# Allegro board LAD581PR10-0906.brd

Outline 320.45 x 178.8 mm; copper layers: TOP, GND1, IN1, GND2, IN2, VCC, IN3, IN4, GND3, IN5, GND4, BOTTOM. Coordinates in mm from the lower left corner of the outline.

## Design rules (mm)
constraint set DEFAULT: min track width 0.114
net group 15/12: nets TBT_A_USB20_NT TBT_A_USB20_PT
net group 18/12: nets H_PECI PECI_KB9012
net group CPU_DP1_0: nets CPU_DP1_N0 CPU_DP1_P0
net group CPU_DP1_0_C: nets CPU_DP1_N0_C CPU_DP1_P0_C
net group CPU_DP1_1: nets CPU_DP1_N1 CPU_DP1_P1
net group CPU_DP1_1_C: nets CPU_DP1_N1_C CPU_DP1_P1_C
net group CPU_DP1_2: nets CPU_DP1_N2 CPU_DP1_P2
net group CPU_DP1_2_C: nets CPU_DP1_N2_C CPU_DP1_P2_C
net group CPU_DP1_3: nets CPU_DP1_N3 CPU_DP1_P3
net group CPU_DP1_3_C: nets CPU_DP1_N3_C CPU_DP1_P3_C
net group CPU_DP1_AUX: nets CPU_DP1_AUXN CPU_DP1_AUXP
net group CPU_DP1_AUX_C: nets CPU_DP1_AUXN_C CPU_DP1_AUXP_C
net group CPU_DP2_0: nets CPU_DP2_N0 CPU_DP2_P0
net group CPU_DP2_0_C: nets CPU_DP2_N0_C CPU_DP2_P0_C
net group CPU_DP2_1: nets CPU_DP2_N1 CPU_DP2_P1
net group CPU_DP2_1_C: nets CPU_DP2_N1_C CPU_DP2_P1_C
net group CPU_DP2_2: nets CPU_DP2_N2 CPU_DP2_P2
net group CPU_DP2_2_C: nets CPU_DP2_N2_C CPU_DP2_P2_C
net group CPU_DP2_3: nets CPU_DP2_N3 CPU_DP2_P3
net group CPU_DP2_3_C: nets CPU_DP2_N3_C CPU_DP2_P3_C
net group CPU_DP2_AUX: nets CPU_DP2_AUXN CPU_DP2_AUXP
net group CPU_DP2_AUX_C: nets CPU_DP2_AUXN_C CPU_DP2_AUXP_C
net group DDR-ALERT: nets DDR_A_ALERT# DDR_B_ALERT#
net group DDRA-CLK: nets M_CLK_DDR1 M_CLK_DDR#1
net group DDRB-CLK: nets M_CLK_DDR2 M_CLK_DDR#2
net group DIFFPAIR47: nets M_CLK_DDR0 M_CLK_DDR#0
net group DIFFPAIR50: nets M_CLK_DDR3 M_CLK_DDR#3
net group DIFFPAIR85: nets TP_CLK TP_DATA
net group DIFFPAIR91: nets TBTA_SBU1 TBTA_SBU2
net group DIFFPAIR93: nets DISP_CLK_AUXP_CONN DISP_DAT_AUXN_CONN
net group DIFFPAIR126: nets PEG_CRX_GTX_N9 PEG_CRX_GTX_P9
net group DIFFPAIR127: nets PEG_CRX_GTX_C_N10 PEG_CRX_GTX_C_P10
net group DIFFPAIR128: nets PEG_CRX_GTX_N10 PEG_CRX_GTX_P10
net group DIFFPAIR129: nets PEG_CRX_GTX_N8 PEG_CRX_GTX_P8
net group DIFFPAIR130: nets PEG_CRX_GTX_C_N11 PEG_CRX_GTX_C_P11
net group DIFFPAIR131: nets PEG_CRX_GTX_N11 PEG_CRX_GTX_P11
net group DIFFPAIR132: nets PEG_CTX_GRX_N10 PEG_CTX_GRX_P10
net group DIFFPAIR133: nets PEG_CTX_C_GRX_N10 PEG_CTX_C_GRX_P10
net group DIFFPAIR134: nets PEG_CTX_GRX_N11 PEG_CTX_GRX_P11
net group DIFFPAIR135: nets PEG_CTX_C_GRX_N11 PEG_CTX_C_GRX_P11
net group DIFFPAIR136: nets PEG_CTX_GRX_N9 PEG_CTX_GRX_P9
net group DIFFPAIR137: nets PEG_CTX_C_GRX_N8 PEG_CTX_C_GRX_P8
net group DIFFPAIR138: nets PEG_CTX_GRX_N8 PEG_CTX_GRX_P8
net group DIFFPAIR139: nets PEG_CTX_C_GRX_N9 PEG_CTX_C_GRX_P9
net group DIFFPAIR140: nets PEG_CTX_C_GRX_N7 PEG_CTX_C_GRX_P7
net group DIFFPAIR141: nets PEG_CTX_C_GRX_N5 PEG_CTX_C_GRX_P5
net group DIFFPAIR142: nets PEG_CTX_C_GRX_N6 PEG_CTX_C_GRX_P6
net group DIFFPAIR143: nets PEG_CTX_C_GRX_N4 PEG_CTX_C_GRX_P4
net group DIFFPAIR144: nets PEG_CTX_C_GRX_N3 PEG_CTX_C_GRX_P3
net group DIFFPAIR145: nets PEG_CTX_C_GRX_N2 PEG_CTX_C_GRX_P2
net group DIFFPAIR146: nets PEG_CTX_C_GRX_N1 PEG_CTX_C_GRX_P1
net group DIFFPAIR147: nets PEG_CTX_C_GRX_N0 PEG_CTX_C_GRX_P0
net group DIFFPAIR148: nets PEG_CRX_GTX_C_N9 PEG_CRX_GTX_C_P9
net group DIFFPAIR149: nets PEG_CRX_GTX_C_N8 PEG_CRX_GTX_C_P8
net group DIFFPAIR151: nets FBC_WCK23 FBC_WCK23#
net group DIFFPAIR152: nets FBC_WCK67 FBC_WCK67#
net group DIFFPAIR153: nets FBB_WCK23 FBB_WCK23#
net group DIFFPAIR154: nets FBB_CLK0 FBB_CLK0#
net group DIFFPAIR155: nets FBB_CLK1 FBB_CLK1#
net group DIFFPAIR156: nets FBB_WCK67 FBB_WCK67#
net group DIFFPAIR157: nets FBA_WCK23 FBA_WCK23#
net group DIFFPAIR158: nets FBA_CLK0 FBA_CLK0#
net group DIFFPAIR159: nets FBA_CLK1 FBA_CLK1#
net group DIFFPAIR160: nets FBA_WCK67 FBA_WCK67#
net group DIFFPAIR163: nets DMIC_CLK1_R DMIC_DATA1_R
net group DIFFPAIR164: nets EC_ESB_CLK EC_ESB_DAT
net group DIFFPAIR165: nets FBC_CLK1 FBC_CLK1#
net group DIFFPAIR166: nets FBC_WCK45 FBC_WCK45#
net group DIFFPAIR167: nets FBC_WCK01 FBC_WCK01#
net group DIFFPAIR168: nets FBA_WCK01 FBA_WCK01#
net group DIFFPAIR175: nets HDMI_CTRLCLK HDMI_CTRLDAT
net group DIFFPAIR176: nets I2CC_SCL I2CC_SDA
net group DIFFPAIR177: nets VGA_SMB_CK2 VGA_SMB_DA2
net group DIFFPAIR178: nets I2CC_SCL_R I2CC_SDA_R
net group DIFFPAIR179: nets FBB_WCK45 FBB_WCK45#
net group DIFFPAIR180: nets FBA_WCK45 FBA_WCK45#
net group DIFFPAIR181: nets FBB_WCK01 FBB_WCK01#
net group DP1: nets DDR_A_DQS0 DDR_A_DQS#0
net group DP3: nets DDR_A_DQS2 DDR_A_DQS#2
net group DP5: nets DDR_A_DQS4 DDR_A_DQS#4
net group DP7: nets DDR_A_DQS6 DDR_A_DQS#6
net group DP9: nets DDR_B_DQS0 DDR_B_DQS#0
net group DP11: nets DDR_B_DQS2 DDR_B_DQS#2
net group DP13: nets DDR_B_DQS4 DDR_B_DQS#4
net group DP15: nets DDR_B_DQS6 DDR_B_DQS#6
net group DP17: nets FBC_CLK0 FBC_CLK0#
net group EDP-GPU: nets GPU_AUXN/DDC_C GPU_AUXP/DDC_C
net group PEG_CRX_TTX_12_C: nets PEG_CRX_TTX_N12_C PEG_CRX_TTX_P12_C
net group PEG_CRX_TTX_13_C: nets PEG_CRX_TTX_N13_C PEG_CRX_TTX_P13_C
net group PEG_CRX_TTX_14_C: nets PEG_CRX_TTX_N14_C PEG_CRX_TTX_P14_C
net group PEG_CRX_TTX_15_C: nets PEG_CRX_TTX_N15_C PEG_CRX_TTX_P15_C
net group PEG_CTX_TRX_12_C: nets PEG_CTX_TRX_N12_C PEG_CTX_TRX_P12_C
net group PEG_CTX_TRX_13_C: nets PEG_CTX_TRX_N13_C PEG_CTX_TRX_P13_C
net group PEG_CTX_TRX_14_C: nets PEG_CTX_TRX_N14_C PEG_CTX_TRX_P14_C
net group PEG_CTX_TRX_15_C: nets PEG_CTX_TRX_N15_C PEG_CTX_TRX_P15_C
net group SW_USB20_1: nets SW_USB20_N1 SW_USB20_P1
net group TBTA_DIG_AUD_: nets TBTA_DIG_AUD_N TBTA_DIG_AUD_P
net group TMDS_L_TX0: nets TMDS_L_TX0N TMDS_L_TX0P
net group TMDS_L_TX1: nets TMDS_L_TX1N TMDS_L_TX1P
net group TMDS_L_TX2: nets TMDS_L_TX2N TMDS_L_TX2P
net group TMDS_L_TXC: nets TMDS_L_TXCN TMDS_L_TXCP
net group 10: nets HPOUT-L HPOUT-R REMOTE1+ REMOTE1- REMOTE2+ REMOTE2- REMOTE3+ REMOTE3- SPK_L+_CONN SPK_L-_CONN SPK_R+_CONN SPK_R-_CONN
net group 12: nets CALDERA_RST# CDRA_RST# CFG0 CFG1 CFG2 CFG3 CFG4 CFG5 CFG6 CFG7 CFG8 CFG9 CFG10 CFG11 CFG12 CFG13 CFG14 CFG15 CFG16 CFG17 CFG18 CFG19 CPU_TRIGGER DGPU_HOLD_RST# DGPU_PEX_RST# DGPU_PWROK H_CPUPWRGD H_DRAMRST# H_PM_DOWN H_PM_SYNC_R H_PROCHOT# H_THERMTRIP# H_THERMTRIP#_R H_VCCST_PWRGD PCH_DPWROK PCH_PLTRST# PCH_PWROK PCH_TRIGGER PLTRST_CPU# SYS_PWROK VCCIO_PGOOD VR_HOT#
net group 15: nets CRX_N8 CRX_N9 CRX_N10 CRX_N11 CRX_P8 CRX_P9 CRX_P10 CRX_P11 PBTN_OUT# PCIE_WAKE# PCIECOMP PCIECOMP# PEG_RCOMP USB2_COMP
net group 19/12: nets DP_AUXN_C DP_AUXP_C EDP_TX0#_C EDP_TX0_C EDP_TX1#_C EDP_TX1_C EDP_TX2#_C EDP_TX2_C EDP_TX3#_C EDP_TX3_C GPU_AUXN/DDC GPU_AUXP/DDC GPU_MDP_N0 GPU_MDP_N1 GPU_MDP_N2 GPU_MDP_N3 GPU_MDP_P0 GPU_MDP_P1 GPU_MDP_P2 GPU_MDP_P3 GPU_TX0N GPU_TX0N_C GPU_TX0P GPU_TX0P_C GPU_TX1N GPU_TX1N_C GPU_TX1P GPU_TX1P_C GPU_TX2N GPU_TX2N_C GPU_TX2P GPU_TX2P_C GPU_TX3N GPU_TX3N_C GPU_TX3P GPU_TX3P_C MDP_LANE_N0_C MDP_LANE_N1_C MDP_LANE_N2_C MDP_LANE_N3_C MDP_LANE_P0_C MDP_LANE_P1_C MDP_LANE_P2_C MDP_LANE_P3_C MUX_EDP_A0N MUX_EDP_A0P MUX_EDP_A1N MUX_EDP_A1P MUX_EDP_A2N MUX_EDP_A2P MUX_EDP_A3N MUX_EDP_A3P TMDS_C_TX0N TMDS_C_TX0P TMDS_C_TX1N TMDS_C_TX1P TMDS_C_TX2N TMDS_C_TX2P TMDS_C_TXCN TMDS_C_TXCP TMDS_CTRLCLK_R TMDS_CTRLDAT_R TMDS_R_TX0N TMDS_R_TX0P TMDS_R_TX1N TMDS_R_TX1P TMDS_R_TX2N TMDS_R_TX2P TMDS_R_TXCN TMDS_R_TXCP TMDS_SCLF TMDS_SDAF TMDS_TX0N TMDS_TX0P TMDS_TX1N TMDS_TX1P TMDS_TX2N TMDS_TX2P TMDS_TXCN TMDS_TXCP
net group 20: nets +V_DDR_REFA +V_DDR_REFA_R +V_DDR_REFB +V_DDR_REFB_R TBT_A_AUX_N TBT_A_AUX_N_C TBT_A_AUX_P TBT_A_AUX_P_C TBT_XTAL_25_IN TBT_XTAL_25_OUT XTAL24_IN XTAL24_OUT XTLI XTLO
net group 25: nets EDP_RCOMP
net group AUDIO: nets HDA_SPKR ME_EN PCH_AZ_BITCLK PCH_AZ_CODEC_BITCLK PCH_AZ_CODEC_RST# PCH_AZ_CODEC_RST#_R PCH_AZ_CODEC_SDIN0 PCH_AZ_CODEC_SDOUT PCH_AZ_CODEC_SYNC PCH_AZ_RST# PCH_AZ_SDOUT PCH_AZ_SYNC
net group B+: nets B+
net group DDR-RCOMP: nets DDR_RCOMP0 DDR_RCOMP1 DDR_RCOMP2
net group DDR-STROBE: nets DDR_A_DQS1 DDR_A_DQS3 DDR_A_DQS5 DDR_A_DQS7 DDR_A_DQS#1 DDR_A_DQS#3 DDR_A_DQS#5 DDR_A_DQS#7 DDR_B_DQS1 DDR_B_DQS3 DDR_B_DQS5 DDR_B_DQS7 DDR_B_DQS#1 DDR_B_DQS#3 DDR_B_DQS#5 DDR_B_DQS#7
net group DDRA-CMD: nets DDR_A_BG0 DDR_A_BG1 DDR_A_BS0 DDR_A_BS1 DDR_A_CAS# DDR_A_MA0 DDR_A_MA1 DDR_A_MA2 DDR_A_MA3 DDR_A_MA4 DDR_A_MA5 DDR_A_MA6 DDR_A_MA7 DDR_A_MA8 DDR_A_MA9 DDR_A_MA10 DDR_A_MA11 DDR_A_MA12 DDR_A_MA13 DDR_A_RAS# DDR_A_WE#
net group DDRA-CTL: nets DDR_A_ACT# DDR_A_PAR DDR_CKE0_DIMMA DDR_CKE1_DIMMA DDR_CS0_DIMMA# DDR_CS1_DIMMA# M_ODT0 M_ODT1
net group DDRA-D0: nets DDR_A_D0 DDR_A_D1 DDR_A_D2 DDR_A_D3 DDR_A_D4 DDR_A_D5 DDR_A_D6 DDR_A_D7
net group DDRA-D1: nets DDR_A_D8 DDR_A_D9 DDR_A_D10 DDR_A_D11 DDR_A_D12 DDR_A_D13 DDR_A_D14 DDR_A_D15
net group DDRA-D2: nets DDR_A_D16 DDR_A_D17 DDR_A_D18 DDR_A_D19 DDR_A_D20 DDR_A_D21 DDR_A_D22 DDR_A_D23
net group DDRA-D3: nets DDR_A_D24 DDR_A_D25 DDR_A_D26 DDR_A_D27 DDR_A_D28 DDR_A_D29 DDR_A_D30 DDR_A_D31
net group DDRA-D4: nets DDR_A_D32 DDR_A_D33 DDR_A_D34 DDR_A_D35 DDR_A_D36 DDR_A_D37 DDR_A_D38 DDR_A_D39
net group DDRA-D5: nets DDR_A_D40 DDR_A_D41 DDR_A_D42 DDR_A_D43 DDR_A_D44 DDR_A_D45 DDR_A_D46 DDR_A_D47
net group DDRA-D6: nets DDR_A_D48 DDR_A_D49 DDR_A_D50 DDR_A_D51 DDR_A_D52 DDR_A_D53 DDR_A_D54 DDR_A_D55
net group DDRA-D7: nets DDR_A_D56 DDR_A_D57 DDR_A_D58 DDR_A_D59 DDR_A_D60 DDR_A_D61 DDR_A_D62 DDR_A_D63
net group DDRB-CMD: nets DDR_B_BG0 DDR_B_BG1 DDR_B_BS0 DDR_B_BS1 DDR_B_CAS# DDR_B_MA0 DDR_B_MA1 DDR_B_MA2 DDR_B_MA3 DDR_B_MA4 DDR_B_MA5 DDR_B_MA6 DDR_B_MA7 DDR_B_MA8 DDR_B_MA9 DDR_B_MA10 DDR_B_MA11 DDR_B_MA12 DDR_B_MA13 DDR_B_RAS# DDR_B_WE#
net group DDRB-CTL: nets DDR_B_ACT# DDR_B_PAR DDR_CKE2_DIMMB DDR_CKE3_DIMMB DDR_CS2_DIMMB# DDR_CS3_DIMMB# M_ODT2 M_ODT3
net group DDRB-D0: nets DDR_B_D0 DDR_B_D1 DDR_B_D2 DDR_B_D3 DDR_B_D4 DDR_B_D5 DDR_B_D6 DDR_B_D7
net group DDRB-D1: nets DDR_B_D8 DDR_B_D9 DDR_B_D10 DDR_B_D11 DDR_B_D12 DDR_B_D13 DDR_B_D14 DDR_B_D15
net group DDRB-D2: nets DDR_B_D16 DDR_B_D17 DDR_B_D18 DDR_B_D19 DDR_B_D20 DDR_B_D21 DDR_B_D22 DDR_B_D23
net group DDRB-D3: nets DDR_B_D24 DDR_B_D25 DDR_B_D26 DDR_B_D27 DDR_B_D28 DDR_B_D29 DDR_B_D30 DDR_B_D31
net group DDRB-D4: nets DDR_B_D32 DDR_B_D33 DDR_B_D34 DDR_B_D35 DDR_B_D36 DDR_B_D37 DDR_B_D38 DDR_B_D39
net group DDRB-D5: nets DDR_B_D40 DDR_B_D41 DDR_B_D42 DDR_B_D43 DDR_B_D44 DDR_B_D45 DDR_B_D46 DDR_B_D47
net group DDRB-D6: nets DDR_B_D48 DDR_B_D49 DDR_B_D50 DDR_B_D51 DDR_B_D52 DDR_B_D53 DDR_B_D54 DDR_B_D55
net group DDRB-D7: nets DDR_B_D56 DDR_B_D57 DDR_B_D58 DDR_B_D59 DDR_B_D60 DDR_B_D61 DDR_B_D62 DDR_B_D63
net group DIFFPAIR46: nets MIC_DATA
net group DMI: nets DMI_CRX_PTX_N0 DMI_CRX_PTX_N1 DMI_CRX_PTX_N2 DMI_CRX_PTX_N3 DMI_CRX_PTX_P0 DMI_CRX_PTX_P1 DMI_CRX_PTX_P2 DMI_CRX_PTX_P3 DMI_CTX_PRX_N0 DMI_CTX_PRX_N1 DMI_CTX_PRX_N2 DMI_CTX_PRX_N3 DMI_CTX_PRX_P0 DMI_CTX_PRX_P1 DMI_CTX_PRX_P2 DMI_CTX_PRX_P3
net group EDP-CPU_12_15: nets CPU_EDP_AUX CPU_EDP_AUX# CPU_EDP_AUX#_C CPU_EDP_AUX_C CPU_EDP_N0_C CPU_EDP_N1_C CPU_EDP_N2_C CPU_EDP_N3_C CPU_EDP_P0_C CPU_EDP_P1_C CPU_EDP_P2_C CPU_EDP_P3_C CPU_EDP_TX0N CPU_EDP_TX0P CPU_EDP_TX1N CPU_EDP_TX1P CPU_EDP_TX2N CPU_EDP_TX2P CPU_EDP_TX3N CPU_EDP_TX3P EDP_AUX#_C EDP_AUX_C MUX_EDP_AUXN MUX_EDP_AUXP
net group EMC: nets BOOT_1.2V BST_1.2V BST_3V BST_5V CPU_XDP_TRST# MIC_CLK RJ45_CT0 RJ45_CT1 RJ45_CT2 RJ45_CT3 SPI_MOCLK TBT_EE_CLK TBT_TCK
net group FBA-CMD: nets FBA_CMD0 FBA_CMD1 FBA_CMD2 FBA_CMD3 FBA_CMD4 FBA_CMD5 FBA_CMD6 FBA_CMD7 FBA_CMD8 FBA_CMD9 FBA_CMD10 FBA_CMD11 FBA_CMD12 FBA_CMD13 FBA_CMD14 FBA_CMD15 FBA_CMD16 FBA_CMD17 FBA_CMD18 FBA_CMD19 FBA_CMD20 FBA_CMD21 FBA_CMD22 FBA_CMD23 FBA_CMD24 FBA_CMD25 FBA_CMD26 FBA_CMD27 FBA_CMD28 FBA_CMD29 FBA_CMD30 FBA_CMD31
net group FBA-D0: nets FBA_D0 FBA_D1 FBA_D2 FBA_D3 FBA_D4 FBA_D5 FBA_D6 FBA_D7
net group FBA-D1: nets FBA_D8 FBA_D9 FBA_D10 FBA_D11 FBA_D12 FBA_D13 FBA_D14 FBA_D15
net group FBA-D2: nets FBA_D16 FBA_D17 FBA_D18 FBA_D19 FBA_D20 FBA_D21 FBA_D22 FBA_D23
net group FBA-D3: nets FBA_D24 FBA_D25 FBA_D26 FBA_D27 FBA_D28 FBA_D29 FBA_D30 FBA_D31
net group FBA-D4: nets FBA_D32 FBA_D33 FBA_D34 FBA_D35 FBA_D36 FBA_D37 FBA_D38 FBA_D39
net group FBA-D5: nets FBA_D40 FBA_D41 FBA_D42 FBA_D43 FBA_D44 FBA_D45 FBA_D46 FBA_D47
net group FBA-D6: nets FBA_D48 FBA_D49 FBA_D50 FBA_D51 FBA_D52 FBA_D53 FBA_D54 FBA_D55
net group FBA-D7: nets FBA_D56 FBA_D57 FBA_D58 FBA_D59 FBA_D60 FBA_D61 FBA_D62 FBA_D63
net group FBA_DBI: nets FBA_DBI0 FBA_DBI1 FBA_DBI2 FBA_DBI3 FBA_DBI4 FBA_DBI5 FBA_DBI6 FBA_DBI7
net group FBA_EDC: nets FBA_EDC0 FBA_EDC1 FBA_EDC2 FBA_EDC3 FBA_EDC4 FBA_EDC5 FBA_EDC6 FBA_EDC7
net group FBB_CMD: nets FBB_CMD0 FBB_CMD1 FBB_CMD2 FBB_CMD3 FBB_CMD4 FBB_CMD5 FBB_CMD6 FBB_CMD7 FBB_CMD8 FBB_CMD9 FBB_CMD10 FBB_CMD11 FBB_CMD12 FBB_CMD13 FBB_CMD14 FBB_CMD15 FBB_CMD16 FBB_CMD17 FBB_CMD18 FBB_CMD19 FBB_CMD20 FBB_CMD21 FBB_CMD22 FBB_CMD23 FBB_CMD24 FBB_CMD25 FBB_CMD26 FBB_CMD27 FBB_CMD28 FBB_CMD29 FBB_CMD30 FBB_CMD31
net group FBB_D0: nets FBB_D0 FBB_D1 FBB_D2 FBB_D3 FBB_D4 FBB_D5 FBB_D6 FBB_D7
net group FBB_D1: nets FBB_D8 FBB_D9 FBB_D10 FBB_D11 FBB_D12 FBB_D13 FBB_D14 FBB_D15
net group FBB_D2: nets FBB_D16 FBB_D17 FBB_D18 FBB_D19 FBB_D20 FBB_D21 FBB_D22 FBB_D23
net group FBB_D3: nets FBB_D24 FBB_D25 FBB_D26 FBB_D27 FBB_D28 FBB_D29 FBB_D30 FBB_D31
net group FBB_D4: nets FBB_D32 FBB_D33 FBB_D34 FBB_D35 FBB_D36 FBB_D37 FBB_D38 FBB_D39
net group FBB_D5: nets FBB_D40 FBB_D41 FBB_D42 FBB_D43 FBB_D44 FBB_D45 FBB_D46 FBB_D47
net group FBB_D6: nets FBB_D48 FBB_D49 FBB_D50 FBB_D51 FBB_D52 FBB_D53 FBB_D54 FBB_D55
net group FBB_D7: nets FBB_D56 FBB_D57 FBB_D58 FBB_D59 FBB_D60 FBB_D61 FBB_D62 FBB_D63
net group FBB_DBI: nets FBB_DBI0 FBB_DBI1 FBB_DBI2 FBB_DBI3 FBB_DBI4 FBB_DBI5 FBB_DBI6 FBB_DBI7
net group FBB_EDC: nets FBB_EDC0 FBB_EDC1 FBB_EDC2 FBB_EDC3 FBB_EDC4 FBB_EDC5 FBB_EDC6 FBB_EDC7
net group FBC_CMD: nets FBC_CMD0 FBC_CMD1 FBC_CMD2 FBC_CMD3 FBC_CMD4 FBC_CMD5 FBC_CMD6 FBC_CMD7 FBC_CMD8 FBC_CMD9 FBC_CMD10 FBC_CMD11 FBC_CMD12 FBC_CMD13 FBC_CMD14 FBC_CMD15 FBC_CMD16 FBC_CMD17 FBC_CMD18 FBC_CMD19 FBC_CMD20 FBC_CMD21 FBC_CMD22 FBC_CMD23 FBC_CMD24 FBC_CMD25 FBC_CMD26 FBC_CMD27 FBC_CMD28 FBC_CMD29 FBC_CMD30 FBC_CMD31
net group FBC_D0: nets FBC_D0 FBC_D1 FBC_D2 FBC_D3 FBC_D4 FBC_D5 FBC_D6 FBC_D7
net group FBC_D1: nets FBC_D8 FBC_D9 FBC_D10 FBC_D11 FBC_D12 FBC_D13 FBC_D14 FBC_D15
net group FBC_D2: nets FBC_D16 FBC_D17 FBC_D18 FBC_D19 FBC_D20 FBC_D21 FBC_D22 FBC_D23
net group FBC_D3: nets FBC_D24 FBC_D25 FBC_D26 FBC_D27 FBC_D28 FBC_D29 FBC_D30 FBC_D31
net group FBC_D4: nets FBC_D32 FBC_D33 FBC_D34 FBC_D35 FBC_D36 FBC_D37 FBC_D38 FBC_D39
net group FBC_D5: nets FBC_D40 FBC_D41 FBC_D42 FBC_D43 FBC_D44 FBC_D45 FBC_D46 FBC_D47
net group FBC_D6: nets FBC_D48 FBC_D49 FBC_D50 FBC_D51 FBC_D52 FBC_D53 FBC_D54 FBC_D55
net group FBC_D7: nets FBC_D56 FBC_D57 FBC_D58 FBC_D59 FBC_D60 FBC_D61 FBC_D62 FBC_D63
net group FBC_DBI: nets FBC_DBI0 FBC_DBI1 FBC_DBI2 FBC_DBI3 FBC_DBI4 FBC_DBI5 FBC_DBI6 FBC_DBI7
net group FBC_EDC: nets FBC_EDC0 FBC_EDC1 FBC_EDC2 FBC_EDC3 FBC_EDC4 FBC_EDC5 FBC_EDC6 FBC_EDC7
net group I2C: nets I2C_CLK I2C_DAT TBT_I2C_SCL TBT_I2C_SDA TBTA_I2C_INT TBTB_I2C_INT
net group LAN: nets LAN_MDIN0 LAN_MDIN1 LAN_MDIN2 LAN_MDIN3 LAN_MDIP0 LAN_MDIP1 LAN_MDIP2 LAN_MDIP3 RJ45_MDI0+ RJ45_MDI0- RJ45_MDI1+ RJ45_MDI1- RJ45_MDI2+ RJ45_MDI2- RJ45_MDI3+ RJ45_MDI3-
net group LPC: nets LPC_AD0 LPC_AD1 LPC_AD2 LPC_AD3 LPC_FRAME#
net group MDP-GPU: nets GPU_DPC_AUX GPU_DPC_AUX# MDP_AUX#_SDA MDP_AUX_SCL
net group PCIE: nets PCIE_PRX_DTX_N5 PCIE_PRX_DTX_N5_C PCIE_PRX_DTX_N6 PCIE_PRX_DTX_N9 PCIE_PRX_DTX_N10 PCIE_PRX_DTX_N11 PCIE_PRX_DTX_N12 PCIE_PRX_DTX_N13 PCIE_PRX_DTX_N14 PCIE_PRX_DTX_N15 PCIE_PRX_DTX_N16 PCIE_PRX_DTX_P5 PCIE_PRX_DTX_P5_C PCIE_PRX_DTX_P6 PCIE_PRX_DTX_P9 PCIE_PRX_DTX_P10 PCIE_PRX_DTX_P11 PCIE_PRX_DTX_P12 PCIE_PRX_DTX_P13 PCIE_PRX_DTX_P14 PCIE_PRX_DTX_P15 PCIE_PRX_DTX_P16 PCIE_PTX_DRX_N5 PCIE_PTX_DRX_N5_C PCIE_PTX_DRX_N6 PCIE_PTX_DRX_N6_C PCIE_PTX_DRX_N9 PCIE_PTX_DRX_N9_C PCIE_PTX_DRX_N10 PCIE_PTX_DRX_N10_C PCIE_PTX_DRX_N11 PCIE_PTX_DRX_N11_C PCIE_PTX_DRX_N12 PCIE_PTX_DRX_N12_C PCIE_PTX_DRX_N13 PCIE_PTX_DRX_N13_C PCIE_PTX_DRX_N14 PCIE_PTX_DRX_N14_C PCIE_PTX_DRX_N15 PCIE_PTX_DRX_N15_C PCIE_PTX_DRX_N16 PCIE_PTX_DRX_N16_C PCIE_PTX_DRX_P5 PCIE_PTX_DRX_P5_C PCIE_PTX_DRX_P6 PCIE_PTX_DRX_P6_C PCIE_PTX_DRX_P9 PCIE_PTX_DRX_P9_C PCIE_PTX_DRX_P10 PCIE_PTX_DRX_P10_C PCIE_PTX_DRX_P11 PCIE_PTX_DRX_P11_C PCIE_PTX_DRX_P12 PCIE_PTX_DRX_P12_C PCIE_PTX_DRX_P13 PCIE_PTX_DRX_P13_C PCIE_PTX_DRX_P14 PCIE_PTX_DRX_P14_C PCIE_PTX_DRX_P15 PCIE_PTX_DRX_P15_C PCIE_PTX_DRX_P16 PCIE_PTX_DRX_P16_C
net group PEG: nets PEG_CRX_GTX_N0 PEG_CRX_GTX_N0_C PEG_CRX_GTX_N1 PEG_CRX_GTX_N1_C PEG_CRX_GTX_N2 PEG_CRX_GTX_N2_C PEG_CRX_GTX_N3 PEG_CRX_GTX_N3_C PEG_CRX_GTX_N4 PEG_CRX_GTX_N4_C PEG_CRX_GTX_N5 PEG_CRX_GTX_N5_C PEG_CRX_GTX_N6 PEG_CRX_GTX_N6_C PEG_CRX_GTX_N7 PEG_CRX_GTX_N7_C PEG_CRX_GTX_P0 PEG_CRX_GTX_P0_C PEG_CRX_GTX_P1 PEG_CRX_GTX_P2 PEG_CRX_GTX_P2_C PEG_CRX_GTX_P3 PEG_CRX_GTX_P3_C PEG_CRX_GTX_P4 PEG_CRX_GTX_P4_C PEG_CRX_GTX_P5 PEG_CRX_GTX_P5_C PEG_CRX_GTX_P6 PEG_CRX_GTX_P6_C PEG_CRX_GTX_P7 PEG_CRX_GTX_P7_C PEG_CRX_TTX_N12 PEG_CRX_TTX_N13 PEG_CRX_TTX_N14 PEG_CRX_TTX_N15 PEG_CRX_TTX_P12 PEG_CRX_TTX_P13 PEG_CRX_TTX_P14 PEG_CRX_TTX_P15 PEG_CTX_GRX_N0 PEG_CTX_GRX_N1 PEG_CTX_GRX_N2 PEG_CTX_GRX_N3 PEG_CTX_GRX_N4 PEG_CTX_GRX_N5 PEG_CTX_GRX_N6 PEG_CTX_GRX_N7 PEG_CTX_GRX_P0 PEG_CTX_GRX_P1 PEG_CTX_GRX_P2 PEG_CTX_GRX_P3 PEG_CTX_GRX_P4 PEG_CTX_GRX_P5 PEG_CTX_GRX_P6 PEG_CTX_GRX_P7 PEG_CTX_TRX_N12 PEG_CTX_TRX_N13 PEG_CTX_TRX_N14 PEG_CTX_TRX_N15 PEG_CTX_TRX_P12 PEG_CTX_TRX_P13 PEG_CTX_TRX_P14 PEG_CTX_TRX_P15
net group PEG_CRX_GTX_1_C: nets PEG_CRX_GTX_P1_C
net group PLATFORM-CLK: nets CLK_PCI_LPC CLK_PCIE_DGPU#_C CLK_PCIE_DGPU_C CLK_PCIE_N1 CLK_PCIE_N2 CLK_PCIE_N3 CLK_PCIE_N4 CLK_PCIE_N5 CLK_PCIE_N6 CLK_PCIE_P1 CLK_PCIE_P2 CLK_PCIE_P3 CLK_PCIE_P4 CLK_PCIE_P5 CLK_PCIE_P6 CLK_PEG_GPU CLK_PEG_GPU# CPU_24MHZ_N CPU_24MHZ_P PCH_CPU_BCLK_N PCH_CPU_BCLK_P PCH_CPU_PCIBCLK_N PCH_CPU_PCIBCLK_P PCH_XDP_CLK_N PCH_XDP_CLK_P
net group POWER: nets +0.6VS +0.6VSP +0.9V_CIO +0.9V_DP +0.9V_LVR_OUT +0.9V_PCIE +0.9V_SVR +0.9V_USB +1.2V_DDR +1.2V_VCCPLL_OC +1.2VP +1.8VA_TBTA_LDO +1.8VD_TBTA_LDO +1.35VS_VGA_PGOOD +1V_MPHY +1V_PCH +1V_PCH_PRIM +1V_VCCDSW +1VALWP +1VALWP_B+ +2.5V_MEM +2.5V_MEMP +2.5VOUT +2.5VSP_ON +3.3V_1.8V_DVDD +3.3V_1.8V_DVDD_IO +3.3V_ANA_PCIE +3.3V_ANA_USB2 +3.3V_F383 +3.3V_FLASH +3.3V_LC +3.3V_TBT_SX +3.3V_TBT_SX_R +3V_PCH +3VALW_PCH +3VALW_PD +3VALWP +3VLP +3VS_CAM +3VS_DP +3VS_TBT +3VS_TOUCH +5V_PVDD +5V_USB_PWR1 +5V_USB_PWR2 +5V_USBC_VBUS +5VA +5VALW_LED +5VALWP +5VS +5VS_TP_LED +AVDDH +AVDDL +CODEC_AVDD2 +DVDDL +EC_VCCA +HDMI_5V_OUT +INV_PWR_SRC +LAN_IO +LCDVDD +PVDD +RBIAS +RTC_CELL +TBTA_VBUS +V18R +VCCIOP +VCCST +VCCSTG +VDD_TOUCH +VDDCT_L
net group RTC: nets PCH_RTCRST# PCH_RTCX1 PCH_RTCX2 PCH_SRTCRST#
net group SENSE: nets VCCGT_SENSE VCCIO_SENSE VCCSA_SENSE VCCSENSE VSSGT_SENSE VSSIO_SENSE VSSSA_SENSE VSSSENSE
net group SMBUS: nets CLK_SMB CPU_DDC1CLK CPU_DDC1DATA CPU_DDC2CLK CPU_DDC2DATA DAT_SMB EC_SMB_CK1 EC_SMB_CK2 EC_SMB_DA1 EC_SMB_DA2 IN1_PEQ# IN2_PEQ# PCH_SMBCLK PCH_SMBDATA SML0CLK SML0DATA SML1CLK SML1DATA
net group SPI: nets PCH_SPI_CLK PCH_SPI_CLK_R PCH_SPI_CS# PCH_SPI_HOLD# PCH_SPI_HOLD#_R PCH_SPI_SI PCH_SPI_SI_R PCH_SPI_SO PCH_SPI_SO_R PCH_SPI_WP# PCH_SPI_WP#_R PCH_SYS_PWROK_XDP
net group SVID: nets VR_SVID_ALERT# VR_SVID_CLK VR_SVID_DATA
net group TBT: nets USB3_A_TRX_DTX_N0 USB3_A_TRX_DTX_N1 USB3_A_TRX_DTX_P0 USB3_A_TRX_DTX_P1 USB3_A_TTX_C_DRX_N0 USB3_A_TTX_C_DRX_N1 USB3_A_TTX_C_DRX_P0 USB3_A_TTX_C_DRX_P1 USB3_A_TTX_DRX_N0 USB3_A_TTX_DRX_N1 USB3_A_TTX_DRX_P0 USB3_A_TTX_DRX_P1
net group USB20: nets TBT_A_USB20_L_NB TBT_A_USB20_L_NT TBT_A_USB20_L_PB TBT_A_USB20_L_PT TBT_A_USB20_N TBT_A_USB20_NB TBT_A_USB20_P TBT_A_USB20_PB USB20_CAM_N7_R USB20_CAM_P7_R USB20_N1 USB20_N1_CONN USB20_N2 USB20_N2_CONN USB20_N3 USB20_N3_CONN USB20_N4 USB20_N5 USB20_N6 USB20_N7 USB20_N8 USB20_N8_CONN USB20_P1 USB20_P1_CONN USB20_P2 USB20_P2_CONN USB20_P3 USB20_P3_CONN USB20_P4 USB20_P5 USB20_P6 USB20_P7 USB20_P8 USB20_P8_CONN
net group USB30: nets USB3_CRX_L_DTX_N1 USB3_CRX_L_DTX_N2 USB3_CRX_L_DTX_N4 USB3_CRX_L_DTX_N5 USB3_CRX_L_DTX_P1 USB3_CRX_L_DTX_P2 USB3_CRX_L_DTX_P4 USB3_CRX_L_DTX_P5 USB3_CTX_C_DRX_N1 USB3_CTX_C_DRX_N2 USB3_CTX_C_DRX_N4 USB3_CTX_C_DRX_N5 USB3_CTX_C_DRX_P1 USB3_CTX_C_DRX_P2 USB3_CTX_C_DRX_P4 USB3_CTX_C_DRX_P5 USB3_CTX_C_L_DRX_N1 USB3_CTX_C_L_DRX_N2 USB3_CTX_C_L_DRX_N4 USB3_CTX_C_L_DRX_N5 USB3_CTX_C_L_DRX_P1 USB3_CTX_C_L_DRX_P2 USB3_CTX_C_L_DRX_P4 USB3_CTX_C_L_DRX_P5 USB3RN1 USB3RN2 USB3RN3 USB3RN4 USB3RN5 USB3RP1 USB3RP2 USB3RP3 USB3RP4 USB3RP5 USB3TN1 USB3TN2 USB3TN3 USB3TN4 USB3TN5 USB3TP1 USB3TP2 USB3TP3 USB3TP4 USB3TP5
net group XDP: nets XDP_PRDY# XDP_PREQ# XDP_TMS
nets with their own width: min track width 0.254; nets ECAGND HP2_D_L_C HP2_D_R_C LINE1_L LINE1_R NVVDD_VCC_SENSE NVVDD_VSS_SENSE NVVDDS_VCC_SENSE NVVDDS_VSS_SENSE
nets with their own width: min track width 0.356; nets +1V8_AON
nets with their own width: min track width 0.381; nets MEM_VREF
nets with their own width: min track width 0.406; nets +FBA_VREFC +FBB_VREFC +FBC_VREFC
nets with their own width: min track width 0.508; nets +1.35VS_VGA +1V8_MAIN +1VALW +3V3_SYS +3VALW +3VS +5VALW +FBX_PLLAVDD +IFPX_PLLVDD +VCC_CORE +VCCGT +VCCIO +VCCSA GND GNDA N19616464
nets with their own width: min track width 1.016; nets +1.8VS ISENSEP_L ISENSEP_L_R ISENSEP_R ISENSEP_R_R IVSENSE_L IVSENSE_R RJ45_CT VSENSEN_L VSENSEN_R
nets with their own width: min track width 1.524; nets B+_BIAS
nets with their own width: min track width 5.08; nets +3VS_SSD

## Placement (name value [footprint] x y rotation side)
C2  0.1U_0402_10V6K  [C_0402]  215.09 8.08 90 top
C3  2200P_0402_25V7K  [C_0402]  98.52 92.98 180 bottom
C4  1U_0402_6.3V6K  [C_0402]  147.46 72.6 180 top
C6  0.1U_0402_10V7K  [C_0402]  148.84 77.64 0 top
C7  1U_0402_6.3V6K  [C_0402]  152.46 70.34 0 top
C10  0.1U_0402_10V7K  [C_0402]  152.97 77.64 0 top
C11  0.1U_0402_10V7K  [C_0402]  100.48 93.65 270 bottom
C29  0.1U_0402_16V4Z  [C_0402]  197.69 4.27 90 top
C256  10U_0603_6.3V6M  [C_0603]  62.81 55.76 270 bottom
C257  10U_0603_6.3V6M  [C_0603]  61.54 55.76 270 bottom
C258  0.1U_0402_16V7K  [C_0402]  54.75 60.78 180 bottom
C260  10U_0603_6.3V6M  [C_0603]  63.32 66.51 0 top
C261  10U_0603_6.3V6M  [C_0603]  63.32 65.24 0 top
C262  10U_0603_6.3V6M  [C_0603]  54.3 63.32 90 bottom
C263  0.1U_0402_10V7K  [C_0402]  55.39 63.77 90 bottom
C264  10U_0603_6.3V6M  [C_0603]  56.33 55.7 270 bottom
C265  0.1U_0402_10V7K  [C_0402]  55.12 55.7 270 bottom
C266  10U_0603_6.3V6M  [C_0603]  158.57 60.92 90 top
C267  10U_0603_6.3V6M  [C_0603]  159.84 60.92 90 top
C268  0.01U_0402_16V  [C_0402]  149.87 62.18 90 top
C269  10U_0603_6.3V6M  [C_0603]  147.14 58.13 90 top
C270  0.1U_0402_10V7K  [C_0402]  148.35 58.43 90 top
C617  33P_0402_50V8J  [C_0402]  231.92 44.97 180 top
C618  33P_0402_50V8J  [C_0402]  231.92 44.08 180 top
C620  33P_0402_50V8J  [C_0402]  234.91 3.07 180 top
C621  0.047U_0402_16V4Z  [C_0402]  229.63 27.32 180 top
C622  22U_0402_6.3V8J  [C_0402]  231.93 41.49 180 top
C623  0.047U_0402_16V4Z  [C_0402]  229.63 28.21 180 top
C624  22U_0402_6.3V8J  [C_0402]  234.91 3.96 180 top
C625  0.047U_0402_16V4Z  [C_0402]  234.06 17.3 0 top
C627  0.047U_0402_16V4Z  [C_0402]  234.05 20.84 0 top
C628  33P_0402_50V8J  [C_0402]  234.91 2.18 180 top
C635  22U_0402_6.3V8J  [C_0402]  231.93 42.38 180 top
C636  22U_0402_6.3V8J  [C_0402]  231.93 40.6 180 top
C637  22U_0402_6.3V8J  [C_0402]  234.06 18.19 0 top
C638  22U_0402_6.3V8J  [C_0402]  234.06 19.96 0 top
C2498  0.1U_0402_10V6K  [C_0402]  71.14 58.51 225 bottom
C2500  2200P_0402_25V7K  [C_0402]  107.12 130.35 0 bottom
C2502  2200P_0402_25V7K  [C_0402]  68.55 57.54 225 bottom
C2504  2200P_0402_25V7K  [C_0402]  66.76 59.21 225 bottom
C2505  2200P_0402_25V7K  [C_0402]  192.53 29.11 0 top
C2506  220P_0402_50V8J  [C_0402]  59.94 59.9 0 bottom
C2507  470P_0402_50V7K  [C_0402]  59.94 60.91 0 bottom
C2508  1U_0402_6.3V  [C_0402]  198.59 6.06 180 top
C2509  0.1U_0402_25V6K~D  [C_0402]  203.34 2.89 270 top
C2510  2200P_0402_25V7K  [C_0402]  66.12 59.91 225 bottom
C2511  2200P_0402_25V7K  [C_0402]  220.47 36.79 0 bottom
C2512  10U_0603_6.3V6M  [C_0603]  237.69 15.96 90 top
C2513  10U_0603_6.3V6M  [C_0603]  238.9 15.96 90 top
C2514  10U_0603_6.3V6M  [C_0603]  245.7 14.57 90 top
C2515  10U_0603_6.3V6M  [C_0603]  244.43 14.57 90 top
C2516  0.1U_0402_10V7K  [C_0402]  243.59 17.93 0 top
C2518  0.1U_0402_10V7K  [C_0402]  99.33 87.1 270 bottom
C2519  0.1U_0402_10V7K  [C_0402]  97.94 87.72 180 bottom
C2520  0.1U_0402_10V7K  [C_0402]  153.3 72.16 270 top
C2521  0.1U_0402_10V7K  [C_0402]  297.45 61.49 90 top
C2522  0.1U_0402_10V7K  [C_0402]  151.86 57.81 180 top
C2523  0.1U_0402_10V7K  [C_0402]  59.96 58.95 0 bottom
C2524  0.1U_0402_10V7K  [C_0402]  59.76 61.81 0 bottom
C2525  0.1U_0402_10V7K  [C_0402]  56.53 55.52 0 top
CA1  4.7U_0402_6.3V6M  [C_0402]  28.25 31.7 0 bottom
CA2  0.1U_0402_16V7K  [C_0402]  28.25 32.59 0 bottom
CA3  10U_0603_6.3V6M  [C_0603]  24.96 44.46 0 bottom
CA4  0.1U_0402_16V7K  [C_0402]  25.2 43.39 0 bottom
CA5  10U_0603_6.3V6M  [C_0603]  26.23 45.8 0 bottom
CA6  0.1U_0402_16V7K  [C_0402]  26.47 46.88 0 bottom
CA7  10U_0603_6.3V6M  [C_0603]  27.75 44.46 180 top
CA8  0.1U_0402_16V7K  [C_0402]  27.51 43.39 180 top
CA9  10U_0603_6.3V6M  [C_0603]  27.75 45.67 180 top
CA10  0.1U_0402_16V7K  [C_0402]  27.51 46.75 180 top
CA11  10P_0402_50V8J  [C_0402]  33.65 35.32 0 bottom
CA12  0.1U_0402_16V7K  [C_0402]  31.88 38.23 90 bottom
CA13  4.7U_0402_6.3V6M  [C_0402]  32.77 38.23 90 bottom
CA14  10U_0603_6.3V6M  [C_0603]  23.56 44.21 180 bottom
CA15  0.1U_0402_16V7K  [C_0402]  23.13 43.13 180 bottom
CA16  0.1U_0402_16V7K  [C_0402]  23.82 32.6 270 top
CA17  10U_0603_6.3V6M  [C_0603]  22.74 32.59 270 top
CA18  22P_0402_50V8J  [C_0402]  31.31 32.09 270 bottom
CA19  0.1U_0402_16V7K  [C_0402]  27.58 28.72 135 top
CA20  2.2U_0402_6.3V6M  [C_0402]  24.77 32.59 180 bottom
CA21  2.2U_0402_6.3V6M  [C_0402]  24.68 34.53 180 top
CA23  0.1U_0402_16V7K  [C_0402]  29.09 32.67 270 top
CA24  2.2U_0402_6.3V6M  [C_0402]  21.62 35.75 270 bottom
CA25  2.2U_0402_6.3V6M  [C_0402]  22.87 34.32 90 top
CA26  0.1U_0402_16V7K  [C_0402]  21.04 42.64 180 top
CA27  2.2U_0402_6.3V6M  [C_0402]  21.04 41.75 180 top
CA28  0.1U_0402_16V7K  [C_0402]  26.5 32.59 180 bottom
CA29  10U_0603_6.3V6M  [C_0603]  26.61 31.51 180 bottom
CA30  0.1U_0402_16V7K  [C_0402]  25.59 32.6 270 top
CA31  4.7U_0603_6.3V6M  [C_0603]  26.67 32.53 270 top
CA32  10U_0603_6.3V6M  [C_0603]  23.37 43.07 180 top
CA33  10U_0603_6.3V6M  [C_0603]  21.37 40.69 180 top
CA34  10P_0402_50V8J  [C_0402]  29.72 45.4 90 bottom
CA35  22P_0402_50V8J  [C_0402]  30.87 45.4 90 bottom
CA36  22P_0402_50V8J  [C_0402]  33.46 40.34 0 bottom
CA37  22P_0402_50V8J  [C_0402]  33.46 41.23 0 bottom
CA38  22P_0402_50V8J  [C_0402]  33.46 42.62 0 top
CA39  22P_0402_50V8J  [C_0402]  33.46 42.62 0 bottom
CA40  22P_0402_50V8J  [C_0402]  31.89 40.93 270 top
CA41  0.1U_0402_10V7K  [C_0402]  31.87 37.35 0 bottom
CA42  100P_0201_50V  [C_0201]  15.04 15.48 0 top
CA43  100P_0201_50V  [C_0201]  16.14 23.42 180 top
CA44  0.01U_0201_16V7K  [C_0201]  15.76 25.65 270 top
CA45  680P_0201_50V  [C_0201]  15.19 21.75 90 bottom
CA46  680P_0201_50V  [C_0201]  15.25 16.82 270 bottom
CA47  330U_D2E_6.3VM_R25M  [C_D2E]  15.75 31.11 0 bottom
CA48  100P_0201_50V  [C_0201]  15.75 30.89 270 top
CA49  330U_D2E_6.3VM_R25M  [C_D2E]  18.83 35.54 90 bottom
CA50  100P_0201_50V  [C_0201]  15.7 36.02 180 top
CA51  0.01U_0201_16V7K  [C_0201]  15.21 26.11 90 bottom
CA52  10U_0603_25V6M  [C_0603]  30.68 15.96 270 top
CA53  0.1U_0402_25V7K  [C_0402]  31.62 16.89 90 top
CA54  1000P_0402_50V7K  [C_0402]  30.75 16.89 90 top
CA55  10U_0603_25V6M  [C_0603]  22.11 16.28 270 top
CA56  0.1U_0402_25V7K  [C_0402]  22.55 17.48 0 bottom
CA57  1000P_0402_50V7K  [C_0402]  22.55 18.37 0 bottom
CA58  10U_0402_6.3V6M  [C_0402]  27.5 24.98 270 bottom
CA59  0.1U_0402_16V7K  [C_0402]  26.62 24.95 270 bottom
CA60  0.1U_0402_16V7K  [C_0402]  25.73 24.95 270 bottom
CA61  10U_0603_25V  [C_0603]  21.73 22.19 0 bottom
CA62  0.1U_0402_25V7K  [C_0402]  22.22 21.1 0 bottom
CA63  1000P_0402_50V7K  [C_0402]  22.22 20.21 0 bottom
CA64  10U_0402_6.3V6M  [C_0402]  28.38 26.43 0 bottom
CA65  0.1U_0402_16V7K  [C_0402]  28.38 27.32 0 bottom
CA66  1U_0402_16V6K  [C_0402]  23.13 19.26 180 bottom
CA67  .033U_0603_50V7  [C_0603]  28.65 18.12 0 bottom
CA68  .033U_0603_50V7  [C_0603]  27.76 15.42 180 top
CA69  .033U_0603_50V7  [C_0603]  23.94 15.42 0 top
CA70  .033U_0603_50V7  [C_0603]  22.29 16.27 180 bottom
CA71  1U_0402_16V6K  [C_0402]  29.75 19.15 180 bottom
CA74  0.1U_0402_16V7K  [C_0402]  25.72 26.42 90 bottom
CA77  10U_0402_6.3V6M  [C_0402]  26.76 26.44 90 top
CA78  0.1U_0402_16V7K  [C_0402]  27.62 26.44 90 top
CA79  10U_0603_25V6M  [C_0603]  26.29 13.67 0 bottom
CA80  0.1U_0402_25V7K  [C_0402]  26.53 14.72 0 bottom
CA81  1000P_0402_50V7K  [C_0402]  26.53 15.61 0 bottom
CA82  10U_0603_25V6M  [C_0603]  25.28 13.67 180 bottom
CA83  0.1U_0402_25V7K  [C_0402]  25.1 14.71 180 bottom
CA84  1000P_0402_50V7K  [C_0402]  25.1 15.6 180 bottom
CA85  10U_0402_6.3V6M  [C_0402]  29.98 32.67 270 top
CA87  330P_0402_50V7K  [C_0402]  28.65 14.22 270 bottom
CA88  330P_0402_50V7K  [C_0402]  28.69 14.39 180 top
CA89  330P_0402_50V7K  [C_0402]  23.4 14.39 0 top
CA90  330P_0402_50V7K  [C_0402]  22.06 15.16 180 bottom
CA91  680P_0402_50V8J  [C_0402]  16.13 22.88 0 bottom
CA92  680P_0402_50V8J  [C_0402]  16.7 14.31 0 bottom
CA254  1000P_0402_50V7K  [C_0402]  31.25 13.9 270 bottom
CA255  1000P_0402_50V7K  [C_0402]  28.73 12.36 180 top
CA256  1000P_0402_50V7K  [C_0402]  24.27 12.38 0 top
CA257  1000P_0402_50V7K  [C_0402]  20.22 13.38 180 bottom
CA258  0.1U_0402_10V7K  [C_0402]  19.12 26 0 bottom
CA259  0.1U_0402_10V7K  [C_0402]  36.21 37.69 270 top
CC1  0.22U_0201_6.3V  [C_0201]  173.27 97.56 0 bottom
CC2  0.22U_0201_6.3V  [C_0201]  171.81 98.88 0 bottom
CC3  0.22U_0201_6.3V  [C_0201]  173.2 99.85 0 bottom
CC4  0.22U_0201_6.3V  [C_0201]  171.81 101.12 0 bottom
CC5  0.22U_0201_6.3V  [C_0201]  173.27 102.26 0 bottom
CC6  0.22U_0201_6.3V  [C_0201]  171.81 103.08 0 bottom
CC7  0.22U_0201_6.3V  [C_0201]  173.27 104.15 0 bottom
CC8  0.22U_0201_6.3V  [C_0201]  171.81 105.24 0 bottom
CC9  0.22U_0201_6.3V  [C_0201]  121.24 165.34 90 bottom
CC10  0.22U_0201_6.3V  [C_0201]  122.38 167.12 90 bottom
CC11  0.22U_0201_6.3V  [C_0201]  123.59 165.34 90 bottom
CC12  0.22U_0201_6.3V  [C_0201]  124.79 167.12 90 bottom
CC13  0.22U_0201_6.3V  [C_0201]  173.27 96.93 0 bottom
CC14  0.22U_0201_6.3V  [C_0201]  171.81 97.88 0 bottom
CC15  0.22U_0201_6.3V  [C_0201]  173.2 99.21 0 bottom
CC16  0.22U_0201_6.3V  [C_0201]  171.81 100.46 0 bottom
CC17  0.22U_0201_6.3V  [C_0201]  173.27 101.54 0 bottom
CC18  0.22U_0201_6.3V  [C_0201]  171.81 102.45 0 bottom
CC19  0.22U_0201_6.3V  [C_0201]  173.27 103.45 0 bottom
CC20  0.22U_0201_6.3V  [C_0201]  171.81 104.61 0 bottom
CC21  0.22U_0201_6.3V  [C_0201]  120.6 165.34 90 bottom
CC22  0.22U_0201_6.3V  [C_0201]  121.74 167.12 90 bottom
CC23  0.22U_0201_6.3V  [C_0201]  122.95 165.34 90 bottom
CC24  0.22U_0201_6.3V  [C_0201]  124.16 167.12 90 bottom
CD1  1U_0402_6.3V6K~D  [C_0402]  143.45 50.29 270 top
CD2  1U_0402_6.3V6K~D  [C_0402]  133.48 50.35 270 top
CD3  1U_0402_6.3V6K~D  [C_0402]  149.41 50.53 0 top
CD4  1U_0402_6.3V6K~D  [C_0402]  149.41 49.64 0 top
CD5  10U_0603_6.3V6M~D  [C_0603]  120.34 50.47 270 top
CD6  10U_0603_6.3V6M~D  [C_0603]  114.24 50.47 270 top
CD7  10U_0603_6.3V6M~D  [C_0603]  110.24 50.47 270 top
CD8  10U_0603_6.3V6M~D  [C_0603]  109.8 41.13 90 top
CD9  10U_0603_6.3V6M~D  [C_0603]  148.85 51.61 0 top
CD10  10U_0603_6.3V6M~D  [C_0603]  148.85 52.81 0 top
CD11  220U_D7_2VM_R6M  [C_EEFSS0D221R]  133.48 69.06 0 top
CD12  1U_0402_6.3V6K~D  [C_0402]  148.04 39.61 180 top
CD13  10U_0603_6.3V6M~D  [C_0603]  148.34 41.13 180 top
CD14  10U_0603_6.3V6M~D  [C_0603]  148.34 38.46 180 top
CD15  10U_0603_6.3V6M~D  [C_0603]  148.34 42.34 180 top
CD16  0.1U_0402_16V7K~D  [C_0402]  146.96 52.75 180 top
CD17  2.2U_0603_6.3V6K~D  [C_0603]  147.2 53.83 180 top
CD18  0.1U_0402_16V7K~D  [C_0402]  124.78 41.25 90 top
CD19  1U_0402_6.3V6K~D  [C_0402]  100.53 37.59 270 top
CD20  1U_0402_6.3V6K~D  [C_0402]  133.55 37.59 270 top
CD21  1U_0402_6.3V6K~D  [C_0402]  104.72 29.08 270 top
CD22  1U_0402_6.3V6K~D  [C_0402]  85.23 28.5 270 top
CD23  10U_0603_6.3V6M~D  [C_0603]  110.81 28.37 90 top
CD24  10U_0603_6.3V6M~D  [C_0603]  120.53 37.64 270 top
CD25  10U_0603_6.3V6M~D  [C_0603]  124.15 37.64 270 top
CD26  10U_0603_6.3V6M~D  [C_0603]  113.54 28.37 90 top
CD27  10U_0603_6.3V6M~D  [C_0603]  150.63 38.08 0 top
CD28  10U_0603_6.3V6M~D  [C_0603]  150.63 39.29 0 top
CD29  0.1U_0402_16V7K~D  [C_0402]  124.77 29.32 0 top
CD30  1U_0402_6.3V6K~D  [C_0402]  150.87 37 0 top
CD31  1U_0402_6.3V6K~D  [C_0402]  150.87 36.11 0 top
CD32  1U_0402_6.3V6K~D  [C_0402]  149.75 29.89 180 top
CD33  220U_D7_2VM_R6M  [C_EEFSS0D221R]  129.59 69.07 180 top
CD34  0.1U_0402_16V7K~D  [C_0402]  147.78 35.67 180 top
CD35  2.2U_0603_6.3V6K~D  [C_0603]  148.34 36.75 180 top
CD69  0.1U_0402_16V7K~D  [C_0402]  107.27 42.84 270 top
CD70  10U_0603_6.3V6M~D  [C_0603]  123.77 50.47 270 top
CD71  10U_0603_6.3V6M~D  [C_0603]  117.16 41.13 90 top
CD72  10U_0603_6.3V6M~D  [C_0603]  122.24 41.13 90 top
CD73  10U_0603_6.3V6M~D  [C_0603]  112.84 41.13 90 top
CD74  1U_0402_6.3V6K~D  [C_0402]  138.82 42.22 270 top
CD75  1U_0402_6.3V6K~D  [C_0402]  95.25 41.25 90 top
CD76  1U_0402_6.3V6K~D  [C_0402]  105.49 41.92 90 top
CD77  1U_0402_6.3V6K~D  [C_0402]  128.27 42.22 270 top
CD78  1U_0402_6.3V6K~D  [C_0402]  100.46 50.41 270 top
CD79  1U_0402_6.3V6K~D  [C_0402]  89.86 50.35 270 top
CD80  1U_0402_6.3V6K~D  [C_0402]  128.33 28.43 0 top
CD81  1U_0402_6.3V6K~D  [C_0402]  138.75 28.42 90 top
CD82  1U_0402_6.3V6K~D  [C_0402]  143.64 37.59 270 top
CD83  1U_0402_6.3V6K~D  [C_0402]  90.05 37.59 270 top
CD84  10U_0603_6.3V6M~D  [C_0603]  112.59 37.64 270 top
CD85  10U_0603_6.3V6M~D  [C_0603]  115.83 37.64 270 top
CD86  10U_0603_6.3V6M~D  [C_0603]  121.92 28.37 90 top
CD87  10U_0603_6.3V6M~D  [C_0603]  110.49 37.64 270 top
CD88  10U_0603_6.3V6M~D  [C_0603]  150.06 28.81 180 top
CD89  10U_0603_6.3V6M~D  [C_0603]  150.06 25.64 180 top
CD90  10U_0603_6.3V6M~D  [C_0603]  150.06 26.84 180 top
CD91  0.1U_0402_16V7K~D  [C_0402]  108.74 41.05 180 top
CD92  0.1U_0402_16V7K~D  [C_0402]  107.71 29.98 90 top
CE1  1U_0402_6.3V  [C_0402]  267.79 35.72 270 top
CE3  0.1U_0402_16V4Z~D  [C_0402]  266.01 35.71 270 top
CE4  22P_0402_50V8J~D  [C_0402]  266.89 34.8 90 top
CE6  1U_0402_6.3V  [C_0402]  271.85 35.71 270 top
CE7  0.1U_0402_16V4Z~D  [C_0402]  270.96 35.71 270 top
CE8  0.1U_0402_16V4Z~D  [C_0402]  268.11 49.67 90 top
CE9  0.1U_0402_16V4Z~D  [C_0402]  269.13 49.67 90 top
CE13  0.1U_0402_16V4Z~D  [C_0402]  271.97 45.13 0 top
CE14  0.1U_0402_16V4Z~D  [C_0402]  271.96 44.21 0 top
CE15  0.1U_0402_16V4Z~D  [C_0402]  271.96 43.32 0 top
CE16  0.1U_0402_16V4Z~D  [C_0402]  271.96 42.43 0 top
CE17  0.1U_0402_16V4Z~D  [C_0402]  271.97 41.51 0 top
CE18  0.1U_0402_16V4Z~D  [C_0402]  271.97 40.56 0 top
CE19  0.1U_0402_16V4Z~D  [C_0402]  72.01 13.27 90 bottom
CE20  22P_0402_50V8J~D  [C_0402]  69.47 13.21 90 bottom
CE22  4.7U_0603_10V  [C_0603]  72.98 3.96 270 top
CE24  0.1U_0402_16V4Z  [C_0402]  187.14 151.15 0 top
CE25  0.1U_0402_16V4Z  [C_0402]  171.72 22.6 90 bottom
CE27  0.1U_0402_16V7K  [C_0402]  85.11 13.73 180 top
CE28  0.1U_0402_10V7K  [C_0402]  101.13 23.31 90 top
CE29  0.1U_0402_10V7K  [C_0402]  97.42 3.59 270 top
CE30  0.1U_0402_10V7K  [C_0402]  91.19 3.65 270 top
CE31  1000P_0402_50V7K  [C_0402]  104.28 8.17 270 top
CE32  1000P_0402_50V7K  [C_0402]  84.19 6.49 0 top
CE33  0.1U_0402_10V7K  [C_0402]  100.22 23.31 90 top
CE34  0.047U_0402_16V4Z  [C_0402]  92.97 3.65 270 top
CE35  100P_0402_50V8J  [C_0402]  105.5 19.47 180 top
CE36  0.1U_0402_10V7K  [C_0402]  92 1.79 0 top
CE38  0.1U_0402_10V7K  [C_0402]  85.11 9.92 180 top
CE40  100P_0402_50V8J  [C_0402]  84.19 15.76 0 top
CE41  0.1U_0402_10V7K  [C_0402]  90.3 3.65 270 top
CE42  0.1U_0402_10V7K  [C_0402]  88.52 23.43 90 top
CE43  0.1U_0402_10V7K  [C_0402]  85.11 11.83 180 top
CE44  0.1U_0402_10V7K  [C_0402]  101.22 3.65 270 top
CE45  0.1U_0402_10V7K  [C_0402]  93.86 3.65 270 top
CE46  0.1U_0402_10V7K  [C_0402]  99.2 26.01 270 top
CE51  0.033U_0402_25V  [C_0402]  84.14 23.31 90 top
CE55  0.1U_0402_16V7K~D  [C_0402]  68.15 11.28 270 top
CE56  0.1U_0402_16V4Z  [C_0402]  71.39 9.21 90 top
CE57  10P_0402_50V8J  [C_0402]  263.58 36.21 0 top
CE58  10P_0402_50V8J  [C_0402]  255.8 41.23 180 top
CE59  10P_0402_50V8J  [C_0402]  268.68 35.72 270 top
CE60  10P_0402_50V8J  [C_0402]  270.07 35.71 270 top
CE61  0.1U_0402_16V4Z  [C_0402]  198.89 155.73 270 top
CE62  0.1U_0402_16V4Z  [C_0402]  116.92 9.79 90 top
CE63  0.1U_0402_16V7K~D  [C_0402]  120.16 6.81 90 top
CE64  0.1U_0402_16V7K  [C_0402]  73.17 1.61 180 top
CE65  10U_0402_6.3V6M  [C_0402]  72.9 1.92 90 bottom
CF4  22U_0805_6.3VAM  [C_0805]  61.95 55.54 180 top
CF5  22U_0805_6.3VAM  [C_0805]  243.51 91.78 0 bottom
CG1  0.1U_0201_6.3V6K  [C_0201]  187.21 61.7 270 bottom
CG2  1U_0402_6.3V6K  [C_0402]  183.02 105.1 90 top
CG3  1U_0402_6.3V6K  [C_0402]  180.61 95.35 270 top
CG4  1U_0402_6.3V6K  [C_0402]  186.18 102.73 0 top
CG5  4.7U_0603_6.3V6M  [C_0603]  178.39 93.43 180 top
CG6  10U_0603_6.3V6M  [C_0603]  180.74 107.59 270 top
CG7  22U_0805_6.3V6M  [C_0805]  177.5 105.79 90 top
CG8  0.22U_0201_6.3V  [C_0201]  176.76 95.59 0 top
CG9  0.22U_0201_6.3V  [C_0201]  176.76 96.16 0 top
CG10  0.22U_0201_6.3V  [C_0201]  176.76 96.8 0 top
CG11  4.7U_0603_6.3V6M  [C_0603]  188.29 88.23 180 top
CG12  10U_0603_6.3V6M  [C_0603]  191.38 70.86 90 bottom
CG13  1U_0402_6.3V6K  [C_0402]  184.62 101.69 180 top
CG14  4.7U_0603_6.3V6M  [C_0603]  179.02 106.2 90 top
CG16  0.22U_0201_6.3V  [C_0201]  176.76 97.37 0 top
CG17  1U_0402_6.3V6K  [C_0402]  184.67 97.5 180 top
CG18  1U_0402_6.3V6K  [C_0402]  187.72 86.4 270 top
CG19  1U_0402_6.3V6K  [C_0402]  191.97 86.4 270 top
CG20  4.7U_0603_6.3V6M  [C_0603]  191.72 88.16 0 top
CG21  10U_0603_6.3V6M  [C_0603]  190.11 70.86 90 bottom
CG22  0.22U_0201_6.3V  [C_0201]  176.76 98 0 top
CG23  1U_0402_6.3V6K  [C_0402]  186.18 101.62 0 top
CG24  22U_0805_6.3V6M  [C_0805]  190.98 73.65 180 bottom
CG25  0.22U_0201_6.3V  [C_0201]  176.76 98.58 0 top
CG26  0.22U_0201_6.3V  [C_0201]  176.76 99.21 0 top
CG27  0.22U_0201_6.3V  [C_0201]  176.76 99.78 0 top
CG28  0.22U_0201_6.3V  [C_0201]  176.76 100.48 0 top
CG29  0.22U_0201_6.3V  [C_0201]  176.76 101.05 0 top
CG30  0.22U_0201_6.3V  [C_0201]  176.76 101.69 0 top
CG31  0.22U_0201_6.3V  [C_0201]  176.76 102.26 0 top
CG32  0.22U_0201_6.3V  [C_0201]  176.76 103.47 0 top
CG33  0.22U_0201_6.3V  [C_0201]  176.76 102.89 0 top
CG34  0.1U_0201_6.3V6K  [C_0201]  187.09 100.16 90 top
CG35  0.22U_0201_6.3V  [C_0201]  176.76 104.1 0 top
CG36  0.22U_0201_6.3V  [C_0201]  176.76 104.67 0 top
CG40  0.1U_0402_10V7K  [C_0402]  186.77 93.83 270 top
CG42  4.7U_0603_6.3V6M  [C_0603]  181.94 105.75 90 top
CG43  4.7U_0603_6.3V6M  [C_0603]  178.39 94.64 180 top
CG47  0.1U_0402_10V7K  [C_0402]  178.27 88.1 180 top
CG48  0.1U_0402_10V7K  [C_0402]  181.47 95.35 270 top
CG49  0.1U_0402_10V7K  [C_0402]  178.27 87.08 180 top
CG51  0.1U_0402_10V7K  [C_0402]  186.77 90.21 270 top
CG53  0.1U_0402_10V7K  [C_0402]  184.79 89.11 0 top
CG54  0.1U_0402_16V7K  [C_0402]  191.01 106.58 0 top
CG55  22U_0805_6.3V6M  [C_0805]  192.95 76.69 0 bottom
CG56  0.1U_0402_16V4Z~D  [C_0402]  206.02 104.48 180 top
CG57  0.1U_0402_16V4Z~D  [C_0402]  205.89 90.45 180 top
CG58  0.1U_0402_16V4Z~D  [C_0402]  201.31 87.62 0 top
CG59  0.1U_0402_10V7K  [C_0402]  197.25 107.42 270 top
CG60  0.1U_0402_10V7K  [C_0402]  206.02 98.32 180 top
CG61  100P_0402_50V8J~D  [C_0402]  199.59 70.95 0 bottom
CG62  10U_0603_25V6M  [C_0603]  205.56 74.89 90 bottom
CG63  10U_0603_25V6M  [C_0603]  205.56 72.03 90 bottom
CG64  220P_0402_50V8J  [C_0402]  195 73.61 90 bottom
CG65  220P_0402_50V8J  [C_0402]  194.13 73.61 90 bottom
CG66  0.1U_0402_16V4Z~D  [C_0402]  170.13 84.4 90 bottom
CG75  22P_0402_50V8J  [C_0402]  173.94 83.1 270 bottom
CG76  22P_0402_50V8J  [C_0402]  173.94 80.4 90 bottom
CG78  820P_0402_25V7  [C_0402]  195.19 135.22 270 bottom
CG79  820P_0402_25V7  [C_0402]  196.1 135.22 270 bottom
CG80  22U_0603_6.3V6M  [C_0603]  212.61 138.05 90 bottom
CG81  22U_0603_6.3V6M  [C_0603]  196.61 131.94 270 bottom
CG82  22U_0603_6.3V6M  [C_0603]  212.61 140.91 90 bottom
CG83  10U_0402_6.3V4Z  [C_0402]  204.69 142.77 180 top
CG84  10U_0402_6.3V4Z  [C_0402]  205.56 141.36 90 top
CG85  10U_0402_6.3V4Z  [C_0402]  205.49 129.06 0 top
CG86  1U_0402_6.3V4Z  [C_0402]  203.79 139.1 270 top
CG87  1U_0402_6.3V4Z  [C_0402]  203.79 141.01 270 top
CG88  1U_0402_6.3V4Z  [C_0402]  202.96 131.67 270 top
CG89  1U_0402_6.3V4Z  [C_0402]  202.96 132.92 90 top
CG90  1U_0402_6.3V4Z  [C_0402]  206.33 130.91 270 top
CG91  1U_0402_6.3V4Z  [C_0402]  206.33 133.17 90 top
CG97  22U_0603_6.3V6M  [C_0603]  193.94 133.27 270 bottom
CG98  22U_0603_6.3V6M  [C_0603]  193.94 130.35 270 bottom
CG99  22U_0603_6.3V6M  [C_0603]  193.88 141.76 90 bottom
CG100  10U_0402_6.3V4Z  [C_0402]  184.35 131.02 270 top
CG101  10U_0402_6.3V4Z  [C_0402]  185.12 140.49 270 top
CG102  10U_0402_6.3V4Z  [C_0402]  192.48 140.23 90 top
CG103  1U_0402_6.3V4Z  [C_0402]  222.2 129.77 270 top
CG104  1U_0402_6.3V4Z  [C_0402]  186.89 139.23 270 top
CG105  1U_0402_6.3V4Z  [C_0402]  184.23 133.11 90 top
CG106  1U_0402_6.3V4Z  [C_0402]  179.66 133.07 270 top
CG113  820P_0402_25V7  [C_0402]  236.63 122.33 180 bottom
CG114  820P_0402_25V7  [C_0402]  236.63 123.21 180 bottom
CG115  22U_0603_6.3V6M  [C_0603]  242.37 122.77 0 bottom
CG116  22U_0603_6.3V6M  [C_0603]  239.51 122.77 0 bottom
CG117  22U_0603_6.3V6M  [C_0603]  233.72 122.77 180 bottom
CG118  10U_0402_6.3V4Z  [C_0402]  239.71 121.94 0 top
CG119  10U_0402_6.3V4Z  [C_0402]  237.3 92.48 0 top
CG120  10U_0402_6.3V4Z  [C_0402]  239.73 121.06 0 top
CG121  1U_0402_6.3V4Z  [C_0402]  236.23 112.36 180 top
CG122  1U_0402_6.3V4Z  [C_0402]  237.11 112.36 0 top
CG123  1U_0402_6.3V4Z  [C_0402]  238.7 109.88 0 top
CG124  1U_0402_6.3V4Z  [C_0402]  239.79 115.28 0 top
CG125  1U_0402_6.3V4Z  [C_0402]  237.12 113.31 0 top
CG126  1U_0402_6.3V4Z  [C_0402]  234.95 101.12 0 top
CG132  22U_0603_6.3V6M  [C_0603]  228.61 138.43 90 bottom
CG133  22U_0603_6.3V6M  [C_0603]  228.61 141.54 90 bottom
CG134  22U_0603_6.3V6M  [C_0603]  228.61 130.07 270 bottom
CG135  10U_0402_6.3V4Z  [C_0402]  221.32 139.34 180 top
CG136  10U_0402_6.3V4Z  [C_0402]  219.85 141.12 90 top
CG137  10U_0402_6.3V4Z  [C_0402]  221.38 141.12 90 top
CG138  1U_0402_6.3V4Z  [C_0402]  219.15 133.7 270 top
CG139  1U_0402_6.3V4Z  [C_0402]  218.25 139.42 0 top
CG140  1U_0402_6.3V4Z  [C_0402]  220.41 138.39 0 top
CG141  1U_0402_6.3V4Z  [C_0402]  219.36 135.47 180 top
CG148  820P_0402_25V7  [C_0402]  234.63 90.26 0 bottom
CG149  820P_0402_25V7  [C_0402]  234.63 88.48 0 bottom
CG150  22U_0603_6.3V6M  [C_0603]  240.15 87.65 0 bottom
CG151  22U_0603_6.3V6M  [C_0603]  228.49 87.65 180 bottom
CG152  22U_0603_6.3V6M  [C_0603]  237.16 87.65 0 bottom
CG153  10U_0402_6.3V4Z  [C_0402]  239.84 78.95 0 top
CG154  10U_0402_6.3V4Z  [C_0402]  239.78 87.78 0 top
CG155  10U_0402_6.3V4Z  [C_0402]  235.85 82.32 90 top
CG156  1U_0402_6.3V4Z  [C_0402]  235.08 77.43 0 top
CG157  1U_0402_6.3V4Z  [C_0402]  241.05 90.77 0 top
CG158  1U_0402_6.3V4Z  [C_0402]  238.95 73.68 0 top
CG159  1U_0402_6.3V4Z  [C_0402]  235.85 75.98 270 top
CG160  1U_0402_6.3V4Z  [C_0402]  242.91 87.08 180 top
CG161  1U_0402_6.3V4Z  [C_0402]  237.11 89.5 0 top
CG167  22U_0603_6.3V6M  [C_0603]  240.65 106.77 0 bottom
CG168  22U_0603_6.3V6M  [C_0603]  239.89 90.77 0 bottom
CG169  22U_0603_6.3V6M  [C_0603]  231.54 91.02 180 bottom
CG170  10U_0402_6.3V4Z  [C_0402]  237.33 97.94 180 top
CG171  10U_0402_6.3V4Z  [C_0402]  240.86 92.48 0 top
CG172  10U_0402_6.3V4Z  [C_0402]  234.82 96.54 0 top
CG173  1U_0402_6.3V4Z  [C_0402]  238.6 98.83 180 top
CG174  1U_0402_6.3V4Z  [C_0402]  234.01 100.21 90 top
CG175  1U_0402_6.3V4Z  [C_0402]  235.79 95.67 270 top
CG176  1U_0402_6.3V4Z  [C_0402]  239.08 92.48 0 top
CG183  10U_0603_25V6M  [C_0603]  201.5 70.64 0 bottom
CG184  10U_0603_6.3V6M  [C_0603]  214.83 88.1 180 top
CG185  10U_0603_6.3V6M  [C_0603]  214.96 90.26 180 top
CG186  10U_0603_6.3V6M  [C_0603]  214.96 94.19 180 top
CG187  10U_0603_6.3V6M  [C_0603]  215.91 96.35 180 top
CG188  10U_0603_6.3V6M  [C_0603]  215.91 100.51 180 top
CG189  10U_0603_6.3V6M  [C_0603]  214.9 104.67 180 top
CG190  10U_0603_6.3V6M  [C_0603]  214.83 108.93 180 top
CG191  10U_0603_6.3V6M  [C_0603]  214.83 110.96 180 top
CG192  1U_0402_6.3V4Z  [C_0402]  206.02 96.86 180 top
CG193  1U_0402_6.3V4Z  [C_0402]  206.02 103.08 180 top
CG194  1U_0402_6.3V4Z  [C_0402]  206.01 107.42 270 top
CG195  1U_0402_6.3V4Z  [C_0402]  205.12 107.42 270 top
CG196  1U_0402_6.3V4Z  [C_0402]  201.5 107.42 270 top
CG197  1U_0402_6.3V4Z  [C_0402]  191.94 108.37 270 top
CG198  1U_0402_6.3V4Z  [C_0402]  199.53 87.62 0 top
CG199  1U_0402_6.3V4Z  [C_0402]  189.82 108.37 270 top
CG200  1U_0402_6.3V4Z  [C_0402]  194.07 107.42 270 top
CG201  1U_0402_6.3V4Z  [C_0402]  194.96 107.42 270 top
CG202  1U_0402_6.3V4Z  [C_0402]  193.18 107.42 270 top
CG203  1U_0402_6.3V4Z  [C_0402]  198.83 107.4 270 top
CG204  1U_0402_6.3V4Z  [C_0402]  199.71 107.38 0 top
CG205  1U_0402_6.3V4Z  [C_0402]  206.02 94.83 180 top
CG206  1U_0402_6.3V4Z  [C_0402]  202.39 107.42 270 top
CG207  1U_0402_6.3V4Z  [C_0402]  205.89 91.97 180 top
CG208  1U_0402_6.3V4Z  [C_0402]  205.89 88.48 180 top
CG209  1U_0402_6.3V4Z  [C_0402]  205.89 87.62 180 top
CG210  1U_0402_6.3V4Z  [C_0402]  198.26 87.53 90 top
CG211  1U_0402_6.3V4Z  [C_0402]  206.21 89.37 180 top
CG212  1U_0402_6.3V4Z  [C_0402]  196.1 107.42 270 top
CG213  1U_0402_6.3V4Z  [C_0402]  194.07 87.4 90 top
CG214  1U_0402_6.3V4Z  [C_0402]  203.15 87.58 90 top
CG215  1U_0402_6.3V4Z  [C_0402]  204.04 87.58 90 top
CG216  10U_0603_6.3V6M  [C_0603]  195.59 78.64 90 top
CG217  10U_0603_6.3V6M  [C_0603]  218.45 83.46 180 top
CG218  10U_0603_6.3V6M  [C_0603]  205.37 78.51 90 top
CG219  10U_0603_6.3V6M  [C_0603]  214.9 106.77 180 top
CG220  22U_0603_6.3V6M  [C_0603]  214.96 92.1 180 top
CG221  22U_0603_6.3V6M  [C_0603]  216.04 78.89 180 top
CG222  22U_0603_6.3V6M  [C_0603]  201.44 78.7 90 top
CG223  22U_0603_6.3V6M  [C_0603]  215.72 112.74 180 top
CG224  22U_0603_6.3V6M  [C_0603]  203.4 78.7 90 top
CG225  22U_0603_6.3V6M  [C_0603]  212.93 77.3 90 top
CG226  22U_0603_6.3V6M  [C_0603]  218.14 81.43 180 top
CG227  22U_0603_6.3V6M  [C_0603]  211.53 77.94 90 top
CG228  22U_0603_6.3V6M  [C_0603]  199.21 78.7 90 top
CG230  0.1U_0402_10V7K  [C_0402]  185.05 87.03 270 top
CG231  10U_0603_6.3V6M  [C_0603]  186.32 76.35 270 bottom
CG232  47U_0805_6.3V6M~D  [C_0805]  187.85 76.5 270 bottom
CG233  0.1U_0402_10V7K  [C_0402]  186.06 95.47 315 top
CG234  0.1U_0402_10V7K  [C_0402]  196.28 87.55 0 top
CG235  0.1U_0402_10V7K  [C_0402]  184.16 87.03 270 top
CG236  0.1U_0402_10V7K  [C_0402]  182.11 86.84 90 top
CG237  0.1U_0402_10V7K  [C_0402]  203.6 107.42 270 top
CG238  0.1U_0402_10V7K  [C_0402]  181.22 86.84 90 top
CG239  22U_0805_6.3VAM  [C_0805]  178.79 85.75 180 top
CG240  0.01U_0402_16V  [C_0402]  191.72 79.08 0 top
CG241  0.1U_0402_16V4Z~D  [C_0402]  172.35 69.95 270 bottom
CG242  470U_D2E_2VM_R9M  [C_D2E]  233.76 129.5 90 bottom
CG243  10U_0603_6.3V6M  [C_0603]  214.83 86.45 180 top
CG244  470U_D2_2VM_R4.5M~D  [C_D1]  204.67 61.31 270 top
CG245  10U_0603_6.3V6M  [C_0603]  178.32 112.17 90 top
CG246  0.1U_0201_6.3V6K  [C_0201]  181.59 59.4 0 top
CG247  22U_0805_6.3VAM  [C_0805]  178.79 89.5 180 top
CG288  22U_0603_6.3V6M  [C_0603]  196.79 71.36 0 bottom
CG289  10U_0603_6.3V6M  [C_0603]  192.17 69.75 180 bottom
CG290  10U_0603_6.3V6M  [C_0603]  192.71 73.95 90 bottom
CG291  4.7U_0402_6.3V6M  [C_0402]  185.88 84.49 270 top
CG292  1U_0402_6.3V4Z  [C_0402]  184.32 85.25 270 top
CG293  0.1U_0201_6.3V6K  [C_0201]  185.84 87.08 0 top
CG294  0.1U_0201_6.3V6K  [C_0201]  184.24 88.43 225 top
CG295  4.7U_0402_6.3V6M  [C_0402]  193.36 83.34 0 top
CG296  4.7U_0402_6.3V6M  [C_0402]  184.69 99.59 180 top
CG297  4.7U_0402_6.3V6M  [C_0402]  189.74 83.81 0 top
CG298  1U_0402_6.3V4Z  [C_0402]  193.36 85.11 0 top
CG299  1U_0402_6.3V4Z  [C_0402]  193.36 84.23 0 top
CG300  1U_0402_6.3V4Z  [C_0402]  189.74 84.7 0 top
CG301  0.1U_0201_6.3V6K  [C_0201]  177.54 91.27 180 top
CG302  0.1U_0201_6.3V6K  [C_0201]  187.05 96.82 270 top
CG303  0.1U_0201_6.3V6K  [C_0201]  189.73 87.59 180 top
CG304  0.1U_0201_6.3V6K  [C_0201]  186.48 96.82 270 top
CG305  0.1U_0201_6.3V6K  [C_0201]  177.54 90.7 180 top
CG306  0.1U_0201_6.3V6K  [C_0201]  184.71 96.29 180 top
CG307  0.1U_0201_6.3V6K  [C_0201]  190.96 87.93 90 top
CG308  0.1U_0402_10V7K  [C_0402]  178.07 125.56 0 top
CG309  0.1U_0402_10V7K  [C_0402]  178.07 126.52 0 top
CG310  1U_0402_6.3V6K  [C_0402]  178.07 127.53 0 top
CG311  4.7U_0603_6.3V6M  [C_0603]  177.7 128.85 0 top
CG312  0.1U_0402_10V7K  [C_0402]  180.8 75.4 0 top
CG313  0.01U_0402_16V7K  [C_0402]  196.61 134.9 0 top
CG314  0.01U_0402_16V7K  [C_0402]  194.2 132.17 180 top
CG315  0.01U_0402_16V7K  [C_0402]  237.06 122.58 0 top
CG316  0.01U_0402_16V7K  [C_0402]  229.31 134.96 180 bottom
CG317  0.01U_0402_16V7K  [C_0402]  236.68 87.97 270 top
CG318  0.01U_0402_16V7K  [C_0402]  237.12 90.51 0 top
CG320  10U_0603_6.3V6M  [C_0603]  196.04 73.75 90 bottom
CG322  1U_0402_6.3V6K  [C_0402]  194.01 77.56 0 top
CG323  1U_0402_6.3V6K~D  [C_0402]  194.39 74.45 0 top
CG324  22U_0603_6.3V6M  [C_0603]  231.54 89.69 180 bottom
CG325  10U_0402_6.3V4Z  [C_0402]  219.98 130.69 90 top
CG326  10U_0402_6.3V4Z  [C_0402]  239.08 90.58 0 top
CG327  10U_0402_6.3V4Z  [C_0402]  185.61 129.12 0 top
CG328  1U_0402_6.3V4Z  [C_0402]  183.67 142.96 180 top
CG329  1U_0402_6.3V4Z  [C_0402]  185.76 142.65 180 top
CG330  1U_0402_6.3V4Z  [C_0402]  187.34 133.9 270 top
CG331  1U_0402_6.3V4Z  [C_0402]  184.22 135.91 0 top
CG332  1U_0402_6.3V4Z  [C_0402]  184.22 135.03 0 top
CG333  1U_0402_6.3V4Z  [C_0402]  222.14 133.7 270 top
CG334  1U_0402_6.3V4Z  [C_0402]  242.65 91.83 90 top
CG335  1U_0402_6.3V4Z  [C_0402]  243.49 77.94 180 top
CG336  1U_0402_6.3V4Z  [C_0402]  186.64 141.71 270 top
CG337  1U_0402_6.3V4Z  [C_0402]  220.36 135.84 90 top
CG338  1U_0402_6.3V4Z  [C_0402]  219.36 134.58 180 top
